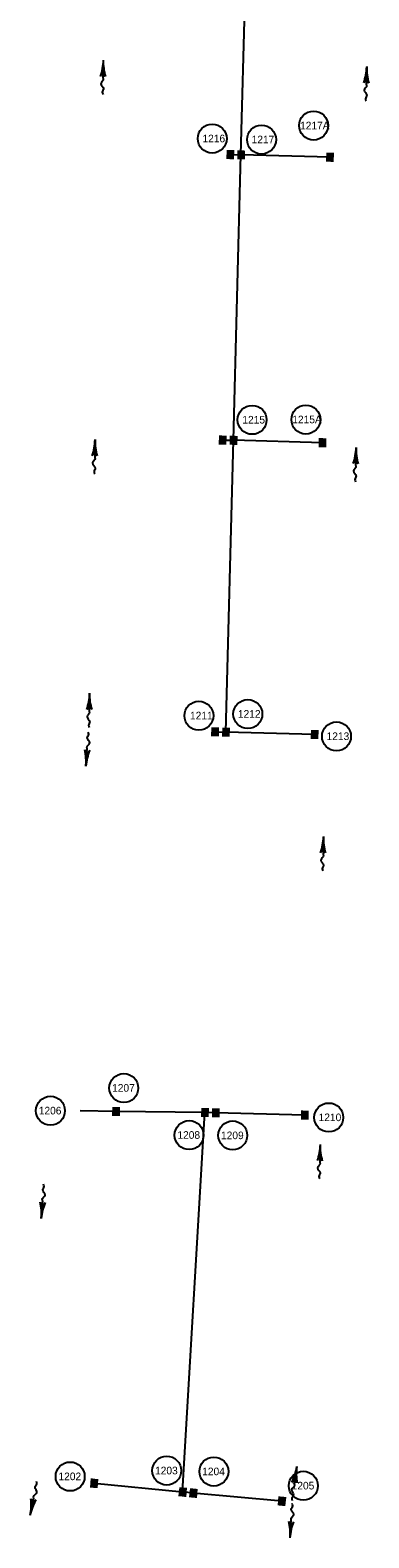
# Model space of a CAD drawing. Extents: x 594534 to 598564, y 225861 to 236229.
# Drawn here: x 598260 to 598527, y 233864 to 235052 of the extents above; entities that cross this region are included whole.
import ezdxf

# ---------------------------------------------------------------- set-up
doc = ezdxf.new("R2010")
doc.units = 0
for name, color, linetype in [('P_DRN_Flow', 7, 'Continuous'), ('P_DRN_Inlet', 7, 'Continuous'), ('P_DRN_SS_UG', 7, 'Continuous'), ('P_DRN_Text', 7, 'Continuous')]:
    doc.layers.add(name, color=color, linetype=linetype)

msp = doc.modelspace()

# ---------------------------------------------------------------- linework, layer by layer
at = {"layer": 'P_DRN_Flow'}
for p, q in [((598317.6, 235028.8), (598317.3, 235014.7)), ((598524.9, 235023.7), (598524.5, 235009.6)), ((598311.1, 234729.9), (598310.8, 234715.7)), ((598516.5, 234723.6), (598516.1, 234709.5)), ((598306.7, 234529.9), (598306.4, 234515.8)), ((598303.9, 234472.4), (598305, 234486.5)), ((598490.9, 234417), (598490.5, 234402.9)), ((598488.3, 234174.5), (598487.9, 234160.4)), ((598268.8, 234116.1), (598269.9, 234130.2)), ((598469.9, 233920.7), (598467.8, 233906.7)), ((598260, 233882.3), (598262.9, 233896.1)), ((598464.5, 233864.5), (598465.5, 233878.6))]:
    msp.add_line(p, q, dxfattribs=at)
for points in [[(598319.3, 235016), (598317.4, 235019.2), (598315.3, 235016.1)], [(598526.5, 235010.8), (598524.6, 235014.1), (598522.5, 235010.9)], [(598312.8, 234717), (598310.9, 234720.3), (598308.8, 234717.1)], [(598518.2, 234710.8), (598516.3, 234714.1), (598514.2, 234710.9)], [(598308.5, 234517.1), (598306.5, 234520.3), (598304.5, 234517.2)], [(598302.9, 234485.3), (598304.7, 234482), (598306.9, 234485)], [(598492.5, 234404.1), (598490.6, 234407.4), (598488.5, 234404.2)], [(598489.9, 234161.6), (598488, 234164.9), (598485.9, 234161.7)], [(598267.8, 234129), (598269.6, 234125.7), (598271.8, 234128.8)], [(598470, 233907.7), (598468.5, 233911.2), (598466.1, 233908.3)], [(598260.6, 233895.2), (598262, 233891.7), (598264.6, 233894.4)], [(598463.4, 233877.4), (598465.2, 233874), (598467.4, 233877.1)]]:
    msp.add_lwpolyline(points, dxfattribs=at)
for centre, start, end in [((598275.7, 235029.7), 341.068, 358.8303), ((598359.5, 235028), 178.8303, 196.5926), ((598482.9, 235024.8), 340.6574, 358.4197), ((598566.8, 235022.5), 178.4197, 196.182), ((598269.1, 234730.7), 341.068, 358.8303), ((598353, 234729), 178.8303, 196.5926), ((598474.6, 234724.8), 340.6574, 358.4197), ((598558.5, 234722.5), 178.4197, 196.182), ((598264.8, 234530.8), 341.068, 358.8303), ((598348.7, 234529.1), 178.8303, 196.5926), ((598262.1, 234475.5), 355.7638, 13.5261), ((598345.8, 234469.3), 158.0015, 175.7638), ((598448.9, 234418.1), 340.6574, 358.4197), ((598532.8, 234415.8), 178.4197, 196.182), ((598446.4, 234175.6), 340.6574, 358.4197), ((598530.2, 234173.3), 178.4197, 196.182), ((598227, 234119.2), 355.7638, 13.5261), ((598310.7, 234113), 158.0015, 175.7638), ((598218.9, 233890.6), 348.5115, 6.2738), ((598301.2, 233873.9), 150.7492, 168.5115), ((598422.7, 233867.6), 355.7638, 13.5261), ((598506.3, 233861.4), 158.0015, 175.7638)]:
    msp.add_arc(centre, 42, start, end, dxfattribs=at)
for centre, major_axis, start_param, end_param in [((598428.4, 233926.7), (6.1, 41.5), 4.402378, 4.712389), ((598511.4, 233914.6), (-6.1, -41.5), 4.712389, 5.0224)]:
    msp.add_ellipse(centre, major_axis=major_axis, ratio=0.999664, start_param=start_param, end_param=end_param, dxfattribs=at)
for points in [[(598317.3, 235014.7), (598317.6, 235013.9), (598315.7, 235010.3), (598317.8, 235006.4), (598316.8, 235003.6), (598317.4, 235001.8)], [(598524.5, 235009.6), (598524.8, 235008.8), (598522.8, 235005.2), (598524.9, 235001.2), (598523.9, 234998.4), (598524.4, 234996.7)], [(598310.8, 234715.7), (598311.1, 234715), (598309.1, 234711.4), (598311.3, 234707.4), (598310.3, 234704.6), (598310.8, 234702.9)], [(598516.1, 234709.5), (598516.4, 234708.7), (598514.4, 234705.2), (598516.5, 234701.2), (598515.5, 234698.4), (598516.1, 234696.6)], [(598306.4, 234515.8), (598306.7, 234515), (598304.8, 234511.5), (598306.9, 234507.5), (598305.9, 234504.7), (598306.5, 234502.9)], [(598305, 234486.5), (598304.7, 234487.3), (598306.9, 234490.8), (598305, 234494.9), (598306.1, 234497.6), (598305.6, 234499.4)], [(598490.5, 234402.9), (598490.8, 234402.1), (598488.8, 234398.5), (598490.9, 234394.5), (598489.9, 234391.7), (598490.4, 234390)], [(598487.9, 234160.4), (598488.2, 234159.6), (598486.2, 234156), (598488.3, 234152), (598487.3, 234149.2), (598487.9, 234147.5)], [(598269.9, 234130.2), (598269.6, 234131), (598271.8, 234134.5), (598269.9, 234138.6), (598271, 234141.3), (598270.5, 234143.1)], [(598262.9, 233896.1), (598262.7, 233896.9), (598265.3, 233900.1), (598263.9, 233904.4), (598265.4, 233907), (598265.1, 233908.8)], [(598467.8, 233906.7), (598468, 233905.9), (598465.7, 233902.6), (598467.3, 233898.4), (598465.9, 233895.7), (598466.3, 233893.9)], [(598465.5, 233878.6), (598465.3, 233879.4), (598467.4, 233882.8), (598465.5, 233886.9), (598466.7, 233889.6), (598466.2, 233891.4)]]:
    msp.add_spline(points, degree=3, dxfattribs=at)
at = {"layer": 'P_DRN_Inlet'}
for p, q in [((598415.3, 234957.9), (598415.1, 234951)), ((598416.2, 234957.9), (598416, 234951)), ((598417.1, 234957.8), (598416.9, 234951)), ((598418, 234957.8), (598417.8, 234950.9)), ((598418.9, 234957.8), (598418.7, 234950.9)), ((598419.8, 234957.8), (598419.6, 234950.9)), ((598423.8, 234957.7), (598423.6, 234950.8)), ((598424.7, 234957.6), (598424.5, 234950.8)), ((598425.6, 234957.6), (598425.4, 234950.7)), ((598426.5, 234957.6), (598426.3, 234950.7)), ((598427.4, 234957.6), (598427.2, 234950.7)), ((598428.3, 234957.5), (598428.1, 234950.7)), ((598493.7, 234955.8), (598493.5, 234948.9)), ((598494.6, 234955.8), (598494.4, 234948.9)), ((598495.5, 234955.8), (598495.3, 234948.9)), ((598496.4, 234955.7), (598496.2, 234948.9)), ((598497.3, 234955.7), (598497.1, 234948.8)), ((598498.2, 234955.7), (598498, 234948.8)), ((598409.3, 234733), (598409.1, 234726.1)), ((598410.2, 234733), (598410, 234726.1)), ((598411.1, 234732.9), (598410.9, 234726.1)), ((598412, 234732.9), (598411.8, 234726)), ((598412.9, 234732.9), (598412.7, 234726)), ((598413.8, 234732.8), (598413.6, 234726)), ((598417.8, 234732.8), (598417.6, 234725.9)), ((598418.7, 234732.7), (598418.5, 234725.9)), ((598419.6, 234732.7), (598419.4, 234725.8)), ((598420.5, 234732.7), (598420.3, 234725.8)), ((598421.4, 234732.6), (598421.2, 234725.8)), ((598422.3, 234732.6), (598422.1, 234725.8)), ((598487.8, 234730.9), (598487.6, 234724)), ((598488.7, 234730.9), (598488.5, 234724)), ((598489.6, 234730.9), (598489.4, 234724)), ((598490.5, 234730.8), (598490.3, 234724)), ((598491.4, 234730.8), (598491.2, 234723.9)), ((598492.3, 234730.8), (598492.1, 234723.9)), ((598403.3, 234503.1), (598403.1, 234496.2)), ((598404.2, 234503), (598404, 234496.2)), ((598405.1, 234503), (598404.9, 234496.1)), ((598406, 234503), (598405.8, 234496.1)), ((598406.9, 234502.9), (598406.7, 234496.1)), ((598407.8, 234502.9), (598407.6, 234496.1)), ((598411.8, 234502.8), (598411.6, 234496)), ((598412.7, 234502.8), (598412.5, 234495.9)), ((598413.6, 234502.8), (598413.4, 234495.9)), ((598414.5, 234502.8), (598414.3, 234495.9)), ((598415.4, 234502.7), (598415.2, 234495.9)), ((598416.3, 234502.7), (598416.1, 234495.8)), ((598481.7, 234501), (598481.5, 234494.1)), ((598482.6, 234501), (598482.4, 234494.1)), ((598483.5, 234500.9), (598483.3, 234494.1)), ((598484.4, 234500.9), (598484.2, 234494)), ((598485.3, 234500.9), (598485.1, 234494)), ((598486.2, 234500.9), (598486, 234494)), ((598325.3, 234203.9), (598325.2, 234197)), ((598326.2, 234203.9), (598326.1, 234197)), ((598327.1, 234203.9), (598327, 234197)), ((598328, 234203.9), (598327.9, 234197)), ((598328.9, 234203.8), (598328.8, 234197)), ((598329.8, 234203.8), (598329.7, 234197)), ((598395.3, 234203.1), (598395.2, 234196.3)), ((598396.2, 234203.1), (598396.1, 234196.2)), ((598397.1, 234203.1), (598397, 234196.2)), ((598398, 234203.1), (598397.9, 234196.2)), ((598398.9, 234203.1), (598398.8, 234196.2)), ((598399.8, 234203.1), (598399.7, 234196.2)), ((598403.8, 234202.9), (598403.7, 234196)), ((598404.7, 234202.9), (598404.6, 234196)), ((598405.6, 234202.9), (598405.5, 234196)), ((598406.5, 234202.9), (598406.4, 234196)), ((598407.4, 234202.8), (598407.3, 234196)), ((598408.3, 234202.8), (598408.2, 234196)), ((598473.8, 234201.1), (598473.7, 234194.2)), ((598474.7, 234201), (598474.6, 234194.2)), ((598475.6, 234201), (598475.5, 234194.2)), ((598476.5, 234201), (598476.4, 234194.1)), ((598477.4, 234201), (598477.3, 234194.1)), ((598478.3, 234201), (598478.2, 234194.1)), ((598308.3, 233911.1), (598307.7, 233904.2)), ((598309.2, 233911), (598308.6, 233904.2)), ((598310.1, 233910.9), (598309.5, 233904.1)), ((598311, 233910.8), (598310.4, 233904)), ((598311.9, 233910.8), (598311.3, 233903.9)), ((598312.8, 233910.7), (598312.2, 233903.8)), ((598378, 233904.2), (598377.4, 233897.3)), ((598378.9, 233904.1), (598378.3, 233897.3)), ((598379.8, 233904), (598379.2, 233897.2)), ((598380.7, 233903.9), (598380.1, 233897.1)), ((598381.6, 233903.9), (598381, 233897)), ((598382.5, 233903.8), (598381.9, 233896.9)), ((598386.4, 233903.3), (598385.8, 233896.5)), ((598387.3, 233903.3), (598386.7, 233896.4)), ((598388.2, 233903.2), (598387.6, 233896.3)), ((598389.1, 233903.1), (598388.5, 233896.3)), ((598390, 233903), (598389.4, 233896.2)), ((598390.9, 233902.9), (598390.3, 233896.1)), ((598456.1, 233897), (598455.5, 233890.1)), ((598457, 233896.9), (598456.4, 233890)), ((598457.9, 233896.8), (598457.3, 233889.9)), ((598458.8, 233896.7), (598458.2, 233889.9)), ((598459.7, 233896.6), (598459.1, 233889.8)), ((598460.6, 233896.6), (598460, 233889.7))]:
    msp.add_line(p, q, dxfattribs=at)
for points in [[(598416.4, 234955.4), (598416.4, 234953.4), (598418.4, 234953.4), (598418.4, 234955.4)], [(598424.9, 234955.2), (598424.9, 234953.2), (598426.9, 234953.1), (598426.9, 234955.1)], [(598494.9, 234953.3), (598494.9, 234951.3), (598496.9, 234951.3), (598496.9, 234953.3)], [(598410.5, 234730.5), (598410.5, 234728.5), (598412.5, 234728.4), (598412.5, 234730.4)], [(598419, 234730.3), (598419, 234728.3), (598421, 234728.2), (598421, 234730.2)], [(598489, 234728.4), (598488.9, 234726.4), (598490.9, 234726.4), (598491, 234728.4)], [(598404.5, 234500.6), (598404.4, 234498.6), (598406.4, 234498.5), (598406.5, 234500.5)], [(598412.9, 234500.4), (598412.9, 234498.4), (598414.9, 234498.3), (598414.9, 234500.3)], [(598482.9, 234498.5), (598482.9, 234496.5), (598484.9, 234496.5), (598484.9, 234498.5)], [(598326.5, 234201.4), (598326.5, 234199.4), (598328.5, 234199.4), (598328.5, 234201.4)], [(598396.5, 234200.7), (598396.5, 234198.7), (598398.5, 234198.6), (598398.5, 234200.6)], [(598405, 234200.4), (598405, 234198.4), (598407, 234198.4), (598407, 234200.4)], [(598475, 234198.6), (598475, 234196.6), (598477, 234196.6), (598477, 234198.6)], [(598309.3, 233908.5), (598309.2, 233906.5), (598311.2, 233906.4), (598311.3, 233908.4)], [(598379, 233901.6), (598378.8, 233899.7), (598380.8, 233899.5), (598381, 233901.5)], [(598387.5, 233900.8), (598387.3, 233898.8), (598389.3, 233898.6), (598389.5, 233900.6)], [(598457.2, 233894.4), (598457, 233892.4), (598459, 233892.2), (598459.2, 233894.2)]]:
    msp.add_lwpolyline(points, close=True, dxfattribs=at)
at = {"layer": 'P_DRN_SS_UG'}
for p, q in [((598425.9, 234954.2), (598432.4, 235199.1)), ((598420, 234729.3), (598425.9, 234954.2)), ((598495.9, 234952.3), (598425.9, 234954.2)), ((598490, 234727.4), (598420, 234729.3)), ((598327.5, 234200.4), (598299.3, 234201)), ((598397.5, 234199.7), (598327.5, 234200.4)), ((598379.9, 233900.6), (598397.5, 234199.7)), ((598406, 234199.4), (598397.5, 234199.7)), ((598476, 234197.6), (598406, 234199.4)), ((598310.3, 233907.5), (598379.9, 233900.6)), ((598388.4, 233899.7), (598379.9, 233900.6)), ((598458.1, 233893.3), (598388.4, 233899.7))]:
    msp.add_line(p, q, dxfattribs=at)
for points in [[(598417.4, 234954.4), (598425.9, 234954.2)], [(598411.5, 234729.5), (598420, 234729.3)], [(598483.9, 234497.5), (598413.9, 234499.3), (598420, 234729.3)], [(598405.4, 234499.6), (598413.9, 234499.3)], [(598406, 234199.4), (598397.5, 234199.7)]]:
    msp.add_lwpolyline(points, dxfattribs=at)
at = {"layer": 'P_DRN_Text'}
for centre in [(598483.1, 234977.3), (598403.3, 234967), (598442.1, 234966.2), (598434.7, 234745.4), (598477, 234745.6), (598431.3, 234513.6), (598392.8, 234512.3), (598501.1, 234496), (598333.7, 234218.9), (598276, 234201), (598495, 234195.7), (598385.1, 234181.8), (598419.4, 234181.6), (598291.5, 233912.8), (598367.5, 233917.4), (598404.6, 233916.7), (598475, 233905.5)]:
    msp.add_circle(centre, 11.4, dxfattribs=at)

# ---------------------------------------------------------------- texts
for s, p in [('1217A', (598472.4, 234974.3)), ('1216', (598395.6, 234964.1)), ('1217', (598434.3, 234963.3)), ('1215', (598427, 234742.5)), ('1215A', (598466.3, 234742.7)), ('1211', (598385.8, 234509.4)), ('1212', (598423.5, 234510.7)), ('1213', (598493.3, 234493.1)), ('1207', (598324.5, 234216)), ('1206', (598266.8, 234198.1)), ('1210', (598487, 234192.8)), ('1208', (598375.9, 234178.9)), ('1209', (598410.2, 234178.6)), ('1203', (598358.3, 233914.5)), ('1204', (598395.4, 233913.8)), ('1202', (598282.3, 233909.9)), ('1205', (598465.8, 233902.6))]:
    msp.add_text(s, height=6, dxfattribs=at).set_placement(p)

doc.saveas('drawing.dxf')
